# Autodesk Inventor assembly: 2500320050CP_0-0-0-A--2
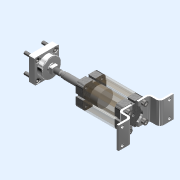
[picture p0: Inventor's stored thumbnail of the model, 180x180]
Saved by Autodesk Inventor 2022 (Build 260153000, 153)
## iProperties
Category: PARTsolutions
Company: METALWORK
Part Number: 2500320050CP_0-0-0-A--2
Catalog Web Link: www.cadenas.de
Description: Compact cylinder series CMPC ISO male piston rod-
Vendor: METALWORK
Document SubType Name: Assembly
Designer: partserver
Manufacturer: METALWORK
Mass: 164.753 g
Surface Area: 678.716 cm^2
Volume: 164.753 cm^3
PSOL_IDENT_0: {$CADENAS_DATA\23d-libs\metalwork\actuators\comp_cyl_ser_cmpc\cmpc_iso_male\cmpc_iso_male_asmtab.prj
PSOL_IDENT_1: },284 {VTYP=3D},{STYP=ASSTAB},{NB=2500320050CP/0-0-0-A--},{LINA=2500320050CP},{NN=Compact cylinder s
PSOL_IDENT_2: eries CMPC ISO male piston rod},{DATE=18.06.2021 08:06:07},{GEOMDATE=21.01.2021 14:41:13},{VERSION=}
PSOL_IDENT_3: ,{LINEID=50},{WBVAR=VE,EX,NS,HUB,HUBST,MAT,SE,AC1,AC2,AC3,AC4,AC5},{WBNUMERIC=HUB,HUBST}  {NB=250032
PSOL_IDENT_4: 0050CP/0-0-0-A--},{LINA=2500320050CP},{KT=DUMMY},{IDNR=},{CODE=2500320050CP},{DI=32},{DX=32},{TP=Cen
PSOL_IDENT_5: tre distance to ISO, male rod},{TYPE=25},{VE=0},{VX='0','Double-acting','1','Double-acting, through-
PSOL_IDENT_6: rod','2','Double-acting, perfored through-rod','3','Single-acting, retracted rod','4','Single-acting
PSOL_IDENT_7: , extended rod','5','Single-acting, through-rod','6','Single-acting, perfored through-rod','A','Doub
PSOL_IDENT_8: le-acting, through-rod, non-rotating'},{EX=0},{EXX= '0','Standard', 'S','Non-magnetic', 'G','No stic
PSOL_IDENT_9: k-slip' },{NS=0},{NX='0','Standard','A','Tandem 2 stages','B','Tandem 3 stages','C','Tandem 4 stages'
PSOL_IDENT_10: ,'P','1st stage','R','2nd stage','T','3rd stage'},{HUB=50},{HUBX1=[5:300]},{HUBX2=050},{HUBST=0},{MA
PSOL_IDENT_11: T=C},{MX= 'C','C45 chromed rod', 'X','Stainless steel rod', 'A','C45 chromed rod, aluminium piston',
PSOL_IDENT_12: 'Z','Stainless steel piston rod and nut, aluminium piston' },{SE=P},{VA=31},{VB=10},{VBA=10},{VC=20
PSOL_IDENT_13: },{VOCF=2},{AC1=0},{AC1X=<'0','','blank.jpg'>, 'S','PISTON ROD NUT - MODEL S','s.jpg', 'GA-M','ROD E
PSOL_IDENT_14: YE - MODEL GA-M','ga_m.jpg','GA','COMPENSATION JOINT - MODEL GA','ga.jpg','GK-M','FORK - MODEL GK-M'
PSOL_IDENT_15: ,'gk_m.jpg','GA-K','SELF ALIGNING ROD COUPLER - MODEL GA-K','ga_k.jpg' },{AC2=0},{AC2X=<'0','','blan
PSOL_IDENT_16: k.jpg'>,'B','HINGE - MODEL B','b.jpg','B+GL','HINGE - MODEL B + GL','b_gl.jpg','BA','HINGE - MODEL B
PSOL_IDENT_17: A','ba.jpg' },{AC3=A},{AC3X='0','','blank.jpg','A','FOOT - MODEL A','a.jpg','X','FLANGE FOR OPPOSITE
PSOL_IDENT_18: CYLINDERS','x.jpg','CF','FRONT FLANGE - MODEL C','cf.jpg','CR','REAR FLANGE - MODEL C','cr.jpg' },{
PSOL_IDENT_19: AC3Y=A},{AC4=},{AC5=},{AC45X='','','blank.jpg','W0952025390','HALL N.O. sensor, vertical insertion 2
PSOL_IDENT_20: .5 m','sov.jpg','W0952225390','HALL N.O. sensor, vertical insertion 2.5 m robotics','sov.jpg','W0952
PSOL_IDENT_21: 029394','HALL N.O. sensor, vertical insertion 300 mm M8 robotics','sov.jpg','W0952022180','REED N.O.
PSOL_IDENT_22: sensor, vertical insertion 2.5 m','sov.jpg','W0952222180','REED N.O. sensor, vertical insertion 2.5
PSOL_IDENT_23: m robotics','sov.jpg','W0952028184','REED N.O. sensor, vertical insertion 300 mm M8 robotics','sov.
PSOL_IDENT_24: jpg','W0952125556','HALL N.O. sensor, vertical insertion 2 m ATEX','sov.jpg','W0952025500','HALL N.O
PSOL_IDENT_25: . sensor, vertical insertion HS 2.5 m','sov.jpg','W0952029504','HALL N.O. sensor, vertical insertion
PSOL_IDENT_26: HS 300 mm M8','sov.jpg','W0952022500','REED N.O. sensor, vertical insertion HS 2.5 m','sov.jpg','W0
PSOL_IDENT_27: 952128184','REED N.O. sensor, vertical insertion HS 300 mm M8','sov.jpg','W095414','REED sensor, T7
PSOL_IDENT_28: SQUARED 2 wires 2.5 m','ssq.jpg','W095415','REED sensor, T7 SQUARED 2 wires 5 m','ssq.jpg','W095416'
PSOL_IDENT_29: ,'REED sensor, T7 SQUARED 2 wires 10 m','ssq.jpg','W09541C','REED sensor, T7 SQUARED 2 wires 2.5 m r
PSOL_IDENT_30: obotics','ssq.jpg','W095411','REED sensor, T7 SQUARED 2 wires 300 mm M8 robotics','ssq.jpg','W095434'
PSOL_IDENT_31: ,'HALL sensor, T7 SQUARED 3 wires 2.5 m','ssq.jpg','W095435','HALL sensor, T7 SQUARED 3 wires 5 m','
PSOL_IDENT_32: ssq.jpg','W09543C','HALL sensor, T7 SQUARED 3 wires 2.5 m robotics','ssq.jpg','W095431','HALL sensor
PSOL_IDENT_33: , T7 SQUARED 3 wires 300 mm M8 robotics','ssq.jpg','W0955A9','HALL sensor, T8 SQUARED 3 wires ATEX 2
PSOL_IDENT_34: m SH.OV.','ssq.jpg'},{INFO=Catalogue},{PPATH=cmpc_iso_male_asmtpl.prj},{A=47},{B=32.5},{B1=},{B2=},
PSOL_IDENT_35: {B3=},{C=12},{C1=},{CH=10},{CH1=17},{D=48.5},{E=6},{F=4},{G=44.5},{H=7.5},{H1=37},{L=4},{N=50.5},{N1=
PSOL_IDENT_36: },{N2=},{O=M6},{O1=5.2},{P1=},{P2=},{Q=G1/8},{R=M10x1.25},{S=22},{S1=6.0},{T=},{U=},{V=},{Z=},{WG=40
PSOL_IDENT_37: 4.50},{WGX=246},{VER=12},{ACALG1=},{ACALG2=},{ACALG3= _ A},{DIALG=32},{SEX= 'P', 'Polyurethane' }
NB: 2500320050CP/0-0-0-A--
NN: Compact cylinder series CMPC ISO male piston rod
NBSYN: $CODE./$HUBST.-$AC1.-$AC2.-$AC3.-$AC4.-$AC5.
LINA: 2500320050CP
CATALOG: Metalwork
CODE: 2500320050CP
DI: 32
TP: Centre distance to ISO, male rod
VE: Double-acting
EX: Standard
HUB: 50
HUBST: 0
MAT: C45 chromed rod
SE: Polyurethane
AC3: FOOT - MODEL A
INFO: Catalogue
A: 47
B: 32.5
C: 12
CH: 10
CH1: 17
D: 48.5
E: 6
F: 4
G: 44.5
H: 7.5
H1: 37
L: 4
N: 50.5
O: M6
O1: 5.2
Q: G1/8
R: M10x1.25
S: 22
S1: 6
WG: 404.5
SUPPLIER: METALWORK
ARTICLENO: 2500320050CP/0-0-0-A--
BOMINFO: 2500320050CP
CREATOR: CADENAS GmbH
Title: 2500320050CP
Author: Cadenas PARTsolutions
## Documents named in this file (9)
- C:\Users\admin\Desktop\inventor\sistema_piegatura2\2500320050CP_0-0-0-A--2.iam
- C:\Users\admin\Desktop\inventor\sistema_piegatura2\250-32-CMPC-HF.ipt
- C:\Users\admin\Desktop\inventor\sistema_piegatura2\250-32_50-CMPC-BR.ipt
- C:\Users\admin\Desktop\inventor\sistema_piegatura2\250-32-CMPC-HR.ipt
- C:\Users\admin\Desktop\inventor\sistema_piegatura2\250-32_50-CMPC-PR.ipt
- C:\Users\admin\Desktop\inventor\sistema_piegatura2\W0950326021-13.ipt
- C:\Users\admin\Desktop\inventor\sistema_piegatura2\W0950322001-31_Z.ipt
- C:\Users\admin\Desktop\inventor\sistema_piegatura2\Cylinder head screw DIN 912 M6x16.ipt
- C:\Users\admin\Desktop\inventor\sistema_piegatura2\Cylinder head screw DIN 912 M6x20.ipt
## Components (15 placed, 8 different names)
1. 250-32-CMPC-HF:1 — Coincidente:8, Coincidente:9, Coincidente:10, Coincidente:11, Angolo:1, Angolo:2
2. 250-32_50-CMPC-BR:1 — Coincidente:1, Coincidente:2, Coincidente:3, Coincidente:8, Coincidente:9, Coincidente:10
3. 250-32-CMPC-HR:1 — Coincidente:1, Coincidente:2, Coincidente:3, Coincidente:12, Coincidente:14, Coincidente:15, Coincidente:16, Coincidente:17, Coincidente:18, Coincidente:19
4. 250-32_50-CMPC-PR:1 — Coincidente:11, Coincidente:12, Angolo:1, Coincidente:13, Rotazionale:1
5. W0950326021-13:1 — Coincidente:13, Angolo:2, Rotazionale:1, Rotazionale:6, Rotazionale:7, Rotazionale:8, Rigido:1
6. W0950322001-31_Z:1 — Coincidente:14, Coincidente:15, Coincidente:16, Rotazionale:2, Rotazionale:3
7. W0950322001-31_Z:2 — Coincidente:17, Coincidente:18, Coincidente:19, Rotazionale:4, Rotazionale:5
8. Cylinder head screw DIN 912 M6x16:1 — Rotazionale:2
9. Cylinder head screw DIN 912 M6x16:2 — Rotazionale:3
10. Cylinder head screw DIN 912 M6x16:3 — Rotazionale:5
11. Cylinder head screw DIN 912 M6x16:4 — Rotazionale:4
12. Cylinder head screw DIN 912 M6x20:1
13. Cylinder head screw DIN 912 M6x20:2
14. Cylinder head screw DIN 912 M6x20:3
15. Cylinder head screw DIN 912 M6x20:4
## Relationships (26: Mate 15, RevoluteJoint 8, Angle 2, WeldJoint 1)
- Coincidente:1 [Mate]: 250-32_50-CMPC-BR:1 ↔ 250-32-CMPC-HR:1
- Coincidente:2 [Mate]: 250-32_50-CMPC-BR:1 ↔ 250-32-CMPC-HR:1
- Coincidente:3 [Mate]: 250-32_50-CMPC-BR:1 ↔ 250-32-CMPC-HR:1
- Coincidente:8 [Mate]: 250-32-CMPC-HF:1 ↔ 250-32_50-CMPC-BR:1
- Coincidente:9 [Mate]: 250-32-CMPC-HF:1 ↔ 250-32_50-CMPC-BR:1
- Coincidente:10 [Mate]: 250-32-CMPC-HF:1 ↔ 250-32_50-CMPC-BR:1
- Coincidente:11 [Mate]: 250-32-CMPC-HF:1 ↔ 250-32_50-CMPC-PR:1
- Coincidente:12 [Mate]: 250-32-CMPC-HR:1 ↔ 250-32_50-CMPC-PR:1
- Angolo:1 [Angle]: 250-32-CMPC-HF:1 ↔ 250-32_50-CMPC-PR:1
- Coincidente:13 [Mate]: 250-32_50-CMPC-PR:1 ↔ W0950326021-13:1
- Angolo:2 [Angle]: 250-32-CMPC-HF:1 ↔ W0950326021-13:1
- Rotazionale:1 [RevoluteJoint]: 250-32_50-CMPC-PR:1 ↔ W0950326021-13:1
- Coincidente:14 [Mate]: 250-32-CMPC-HR:1 ↔ W0950322001-31_Z:1
- Coincidente:15 [Mate]: 250-32-CMPC-HR:1 ↔ W0950322001-31_Z:1
- Coincidente:16 [Mate]: 250-32-CMPC-HR:1 ↔ W0950322001-31_Z:1
- Coincidente:17 [Mate]: 250-32-CMPC-HR:1 ↔ W0950322001-31_Z:2
- Coincidente:18 [Mate]: 250-32-CMPC-HR:1 ↔ W0950322001-31_Z:2
- Coincidente:19 [Mate]: 250-32-CMPC-HR:1 ↔ W0950322001-31_Z:2
- Rotazionale:2 [RevoluteJoint]: W0950322001-31_Z:1 ↔ Cylinder head screw DIN 912 M6x16:1
- Rotazionale:3 [RevoluteJoint]: W0950322001-31_Z:1 ↔ Cylinder head screw DIN 912 M6x16:2
- Rotazionale:4 [RevoluteJoint]: W0950322001-31_Z:2 ↔ Cylinder head screw DIN 912 M6x16:4
- Rotazionale:5 [RevoluteJoint]: W0950322001-31_Z:2 ↔ Cylinder head screw DIN 912 M6x16:3
- Rotazionale:6 [RevoluteJoint]: W0950326021-13:1
- Rotazionale:7 [RevoluteJoint]: W0950326021-13:1
- Rotazionale:8 [RevoluteJoint]: W0950326021-13:1
- Rigido:1 [WeldJoint]: W0950326021-13:1
